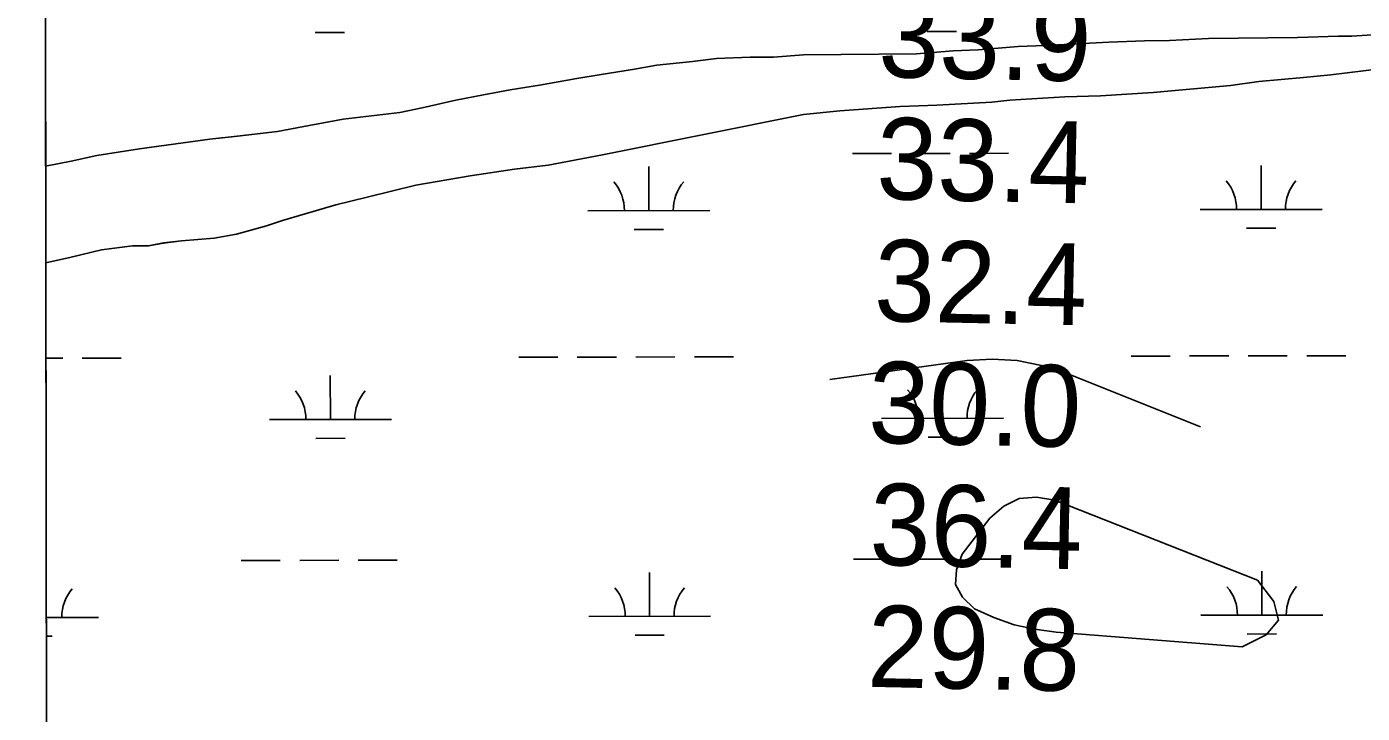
# Model space of a CAD drawing. Extents: x 3329297 to 3367176, y 649250 to 674653.
# Drawn here: x 3333403 to 3334498, y 661713 to 662276 of the extents above; entities that cross this region are included whole.
import ezdxf

# ---------------------------------------------------------------- set-up
doc = ezdxf.new("R2010")
doc.units = 0
for name, color, linetype in [('V-GRID-FRAM', 7, 'Continuous'), ('V-RIVR-EDGE', 7, 'Continuous'), ('V-RIVR-RANG', 7, 'Continuous'), ('V-SITE-VEGE', 7, 'Continuous'), ('V-TOPO-MINR', 7, 'Continuous'), ('V-WETL-SWMP', 7, 'Continuous')]:
    doc.layers.add(name, color=color, linetype=linetype)

msp = doc.modelspace()

# ---------------------------------------------------------------- linework, layer by layer
at = {"layer": 'V-GRID-FRAM'}
msp.add_lwpolyline([(3333403.5, 672816.3), (3364945.5, 672875.9), (3364987.9, 654691.7), (3333429.9, 654632), (3333403.5, 672816.3)], dxfattribs=at)
at = {"layer": 'V-RIVR-EDGE'}
msp.add_spline([(3333408.7, 669402.3), (3333456.2, 669390.7), (3333480.6, 669386.5), (3333498.4, 669381.9), (3333510.9, 669380.2), (3333522.1, 669375.2), (3333537.8, 669370.2), (3333569.3, 669364.3), (3333591.6, 669358.9), (3333623.1, 669349.7), (3333650.9, 669341.3), (3333676.1, 669333), (3333726.3, 669319.2), (3333778.9, 669302), (3333791.7, 669299.5), (3333813.6, 669293.3), (3333833.9, 669285.7), (3333853.8, 669277.4), (3333866.2, 669277.4), (3333927.5, 669258.6), (3333978.9, 669241), (3334054.7, 669220.1), (3334082, 669212.6), (3334104.4, 669205.9), (3334133.4, 669195.1), (3334212.1, 669170), (3334258.9, 669154.5), (3334287.5, 669144.9), (3334323.9, 669134.5), (3334362.8, 669121.1), (3334397.6, 669109.4), (3334435.3, 669094.8), (3334441.9, 669091.5), (3334451.9, 669089.8), (3334461, 669084), (3334464.7, 669082.7), (3334470.5, 669083.6), (3334476.3, 669080.2), (3334476.7, 669076.1), (3334486.6, 669072.7), (3334503.2, 669071.9), (3334523.5, 669067.3), (3334538.4, 669061.4), (3334550.4, 669055.2), (3334564.9, 669046.8), (3334575.7, 669042.7), (3334598.9, 669036.4), (3334626.2, 669030.9), (3334690.8, 669018.8), (3334721.1, 669015.8), (3334733.1, 669015.8), (3334745.1, 669011.2), (3334755.1, 669009.5), (3334769.6, 669008.6), (3334791.1, 669004.4), (3334799.8, 669004.4), (3334813.5, 669004.8), (3334832.6, 668999.8), (3334841.7, 668998.5), (3334844.6, 668994.8), (3334857, 668990.2), (3334864, 668983.9), (3334870.2, 668977.7), (3334876.8, 668970.2), (3334882.2, 668968.6), (3334894.6, 668965.6), (3334904.2, 668965.6), (3334918.3, 668964.3), (3334926.6, 668963.5), (3334936.1, 668958.5), (3334945.2, 668949.3), (3334956.8, 668941), (3334959.7, 668941.4), (3334971.7, 668941.4), (3334983.3, 668941.8), (3334993.2, 668938.9), (3335003.6, 668932.2), (3335011.4, 668925.1), (3335021.8, 668920.1), (3335034.2, 668916), (3335054.9, 668911.8), (3335057, 668908.9), (3335064.8, 668903.9), (3335073.5, 668900.1), (3335081, 668898), (3335087.6, 668898), (3335095.1, 668898), (3335097.6, 668895.1), (3335105, 668888.4), (3335114.1, 668882.2), (3335138.1, 668873), (3335159.7, 668864.2), (3335185.7, 668850.5), (3335195.2, 668838.9), (3335211, 668830.1), (3335229.2, 668825.5), (3335249.9, 668817.6), (3335252.4, 668811.4), (3335261.5, 668805.6), (3335272.7, 668798.5), (3335296.3, 668792.6), (3335327.3, 668778.4), (3335359.2, 668761.8), (3335399.3, 668739.7), (3335432.5, 668723.5), (3335466.4, 668708.1), (3335508.6, 668689.3), (3335535.5, 668674.3), (3335584, 668653.1), (3335614.6, 668638.1), (3335645.3, 668624.7), (3335682.1, 668600.6), (3335715.2, 668580.6), (3335752.5, 668561.5), (3335771.9, 668553.1), (3335793.9, 668548.5), (3335846.4, 668524.7), (3335870.9, 668514.7), (3335887.9, 668509.3), (3335894.9, 668501), (3335912.7, 668488.1), (3335927.6, 668478.1), (3335958.6, 668466.4), (3335986.8, 668452.7), (3336001.3, 668442.7), (3336018.7, 668434.4), (3336038.9, 668426.9), (3336117.2, 668387.3), (3336184.2, 668349), (3336223.1, 668326.5), (3336257.5, 668305.7), (3336289.4, 668284.5), (3336317.1, 668269.5), (3336332.8, 668261.6), (3336456.6, 668198.7), (3336509.2, 668170.8), (3336541.4, 668152.9), (3336585.7, 668130), (3336625.9, 668110.8), (3336652.8, 668097.9), (3336753.4, 668040), (3336798.1, 668013.8), (3336819.6, 668001.3), (3336844, 667986.8), (3336862.2, 667973.9), (3336893.7, 667952.2), (3336928, 667933.1), (3336960.3, 667914.8), (3336990.5, 667894.8), (3337029.4, 667867.8), (3337069.1, 667842.4), (3337101, 667829.5), (3337126.7, 667818.2), (3337166, 667790.3), (3337200.4, 667767.9), (3337228.5, 667747.5), (3337263.3, 667726.3), (3337288.9, 667709.2), (3337372.5, 667657.2), (3337387.8, 667642.6), (3337413.9, 667621.9), (3337448.6, 667598.6), (3337473.4, 667578.6), (3337509, 667550.7), (3337579.4, 667503.3), (3337621.1, 667469.6), (3337665, 667431), (3337708, 667391.1), (3337739.8, 667359.1), (3337772.9, 667327.1), (3337812.2, 667288.5), (3337827.1, 667271.4), (3337829.5, 667264.4), (3337842.8, 667251.5), (3337873.4, 667227.8), (3337886.2, 667214.9), (3337903.2, 667197.9), (3337949.4, 667144.7), (3337971.4, 667123.5), (3337996.2, 667096.5), (3338024.3, 667069.9), (3338047, 667044.6), (3338075.5, 667011.8), (3338104.9, 666976.9), (3338113.6, 666965.2), (3338176.8, 666889.6), (3338206.1, 666850.2), (3338224.3, 666825.3), (3338246.2, 666798.3), (3338263.5, 666774.2), (3338301.9, 666718.6), (3338311.9, 666704.5), (3338328, 666683.3), (3338335.4, 666667.9), (3338348.6, 666644.3), (3338362.6, 666627.2), (3338385.4, 666599.4), (3338404.4, 666574.5), (3338412.6, 666562), (3338414.7, 666551.3), (3338422.1, 666533), (3338443.1, 666494), (3338455.9, 666472), (3338475.4, 666449.6), (3338483.2, 666442.9), (3338498.1, 666425), (3338521.6, 666381.9), (3338562.5, 666317.5), (3338585.6, 666290.5), (3338600.5, 666260.7), (3338619.9, 666220), (3338640.9, 666179.7), (3338652.5, 666165.2), (3338660.7, 666148.6), (3338709, 666053.1), (3338735.4, 666007.5), (3338756.4, 665971.4), (3338777.1, 665937.3), (3338810.1, 665887.1), (3338828.7, 665846.4), (3338853.8, 665796.6), (3338873.6, 665751.8), (3338895.1, 665712.8), (3338903.7, 665692.1), (3338916.5, 665665.9), (3338933.8, 665635.2), (3338944.1, 665609.5), (3338956.5, 665578.8), (3338961.9, 665565.5), (3338976.7, 665543.1), (3338985, 665527.7), (3338995.3, 665511.1), (3339011.8, 665472.1), (3339026.6, 665438.9), (3339039.8, 665412.8), (3339047.6, 665382.9), (3339085.5, 665290), (3339099.5, 665253.9), (3339113.5, 665222.8), (3339126.3, 665192.5), (3339138.7, 665160.5), (3339164.2, 665092.5), (3339180.3, 665056), (3339203.7, 664990.8), (3339215.7, 664956.4), (3339231.3, 664897.5), (3339241.1, 664863.5), (3339253.9, 664825.8), (3339262.1, 664798.4), (3339275.3, 664761.9), (3339290.5, 664724.5), (3339306.2, 664692.2), (3339319, 664656.5), (3339324.3, 664636.6), (3339336.6, 664597.2), (3339352.3, 664567.7), (3339365.5, 664538.2), (3339372.1, 664519.6), (3339374.1, 664493), (3339373.2, 664478.9), (3339373.2, 664471.1), (3339377.3, 664449.9), (3339393.8, 664419.2), (3339410.3, 664384.8), (3339423.5, 664344.9), (3339458.5, 664257.4), (3339470, 664219.2), (3339470.4, 664207.2), (3339477.8, 664185.7), (3339481.1, 664164.9), (3339486.4, 664140), (3339490.1, 664124.3), (3339499.6, 664107.3), (3339512.7, 664069.9), (3339523.8, 664028.4), (3339527.5, 663998.2), (3339528.2, 663969.6), (3339525.7, 663951.8), (3339522.4, 663945.6), (3339521.1, 663939.3), (3339524, 663925.2), (3339554.1, 663875), (3339569.4, 663836), (3339574.3, 663803.7), (3339577.1, 663774.2), (3339586.9, 663730.7), (3339599.7, 663691.3), (3339610.3, 663646.9), (3339623.1, 663615.8), (3339630.5, 663595.9), (3339633.8, 663595.9), (3339643, 663599.2), (3339643, 663594.2), (3339646.2, 663566), (3339654.4, 663535.7), (3339664.3, 663503.8), (3339677, 663465.2), (3339691.9, 663427), (3339697.2, 663406.7), (3339697.2, 663392.2), (3339697.1, 663381), (3339704.9, 663354.5), (3339710.7, 663325.4), (3339723.8, 663284.4), (3339738.7, 663247.4), (3339746.1, 663222.6), (3339747.7, 663203.1), (3339746.4, 663183.6), (3339745.5, 663154.6), (3339745, 663130.5), (3339742.9, 663119.4), (3339739.6, 663107.3), (3339737, 663082.5), (3339735.3, 663062.2), (3339736.9, 663039.8), (3339742.2, 663016.6), (3339743.9, 663011.6), (3339748, 663011.6), (3339751.8, 663009.5), (3339753.8, 663002.4), (3339760, 662996.6), (3339761.2, 662990.8), (3339763.7, 662975.9), (3339763.2, 662954.8), (3339760.7, 662930.3), (3339757.8, 662927.8), (3339749.1, 662927.4), (3339743.3, 662927.4), (3339738.7, 662924.1), (3339735, 662917.9), (3339730.4, 662915.9), (3339727.5, 662912.2), (3339727.1, 662907.6), (3339732.4, 662900.1), (3339737.4, 662884.4), (3339741.9, 662869.4), (3339745.2, 662866.1), (3339748.1, 662867.3), (3339750.6, 662877.3), (3339752.7, 662878.9), (3339754.3, 662875.6), (3339755.6, 662867.7), (3339761.7, 662859), (3339764.2, 662850.7), (3339762.5, 662844.1), (3339761.7, 662822.1), (3339758.3, 662812.6), (3339756.6, 662801.8), (3339759.5, 662784), (3339757.4, 662779.4), (3339754.9, 662768.7), (3339755.3, 662757.1), (3339757.7, 662749.6), (3339761.9, 662739.6), (3339755.6, 662731), (3339746.5, 662711.1), (3339737.7, 662704.1), (3339732.8, 662703.2), (3339730.3, 662699.9), (3339733.6, 662689.6), (3339736.8, 662677.1), (3339737.2, 662668), (3339731.8, 662659.3), (3339726.4, 662644.4), (3339724.3, 662641.1), (3339729.7, 662633.2), (3339729.7, 662627.4), (3339727.2, 662625.3), (3339721.8, 662625.8), (3339721.8, 662615.4), (3339723, 662597.2), (3339722.9, 662560.7), (3339725.3, 662535.4), (3339725.3, 662520.5), (3339726.8, 662486.5), (3339724.3, 662463.3), (3339713, 662438.4), (3339703.9, 662416.9), (3339699.7, 662391.6), (3339692.9, 662333.2), (3339688.2, 662298), (3339687.4, 662274.4), (3339683.6, 662256.1), (3339676.1, 662240), (3339666.1, 662216.8), (3339659.8, 662192.8), (3339656.8, 662171.6), (3339654.7, 662126.1), (3339650.4, 662090.8), (3339644.5, 662058.5), (3339643.7, 662039.5), (3339638.2, 662015.4), (3339634.4, 661998.4), (3339628.6, 661971.9), (3339619, 661945.8), (3339616.5, 661933), (3339617.2, 661907.3), (3339619.6, 661875), (3339617.1, 661854.7), (3339612.9, 661845.6), (3339610.8, 661836.4), (3339610, 661829.8), (3339610, 661820.3), (3339609.9, 661810.7), (3339603.7, 661804.1), (3339600.8, 661799.6), (3339598.7, 661785.1), (3339594.9, 661775.6), (3339590.3, 661759.4), (3339588.6, 661741.2), (3339585.7, 661733.3), (3339580.7, 661727.5), (3339574.1, 661723.8), (3339572.8, 661715.9), (3339571.9, 661693.5), (3339564, 661655), (3339553.9, 661613.6), (3339540.6, 661574.7), (3339527.6, 661533.7), (3339508.4, 661497.2), (3339490.1, 661455.8), (3339486.8, 661446.7), (3339487.1, 661432.6), (3339486.3, 661412.3), (3339484.6, 661404), (3339476.7, 661391.6), (3339467.9, 661378.8), (3339453, 661365.1), (3339446.8, 661363.5), (3339441, 661363.1), (3339433.9, 661354.8), (3339423.5, 661346.2), (3339398.2, 661334.6), (3339381.2, 661326.8), (3339370, 661319.8), (3339357.5, 661305.3), (3339344.6, 661280), (3339333, 661269.7), (3339320.9, 661263.5), (3339313.9, 661263.1), (3339310.2, 661266), (3339308.1, 661271.8), (3339302.7, 661282.2), (3339298.6, 661286.4), (3339290.7, 661288.9), (3339284.9, 661288.9), (3339275, 661285.6), (3339261.3, 661273.2), (3339255.5, 661266.6), (3339248.8, 661265.8), (3339234.7, 661264.6), (3339224.4, 661264.2), (3339216.5, 661259.2), (3339211.9, 661252.2), (3339209.4, 661248.5), (3339211, 661240.6), (3339215.6, 661229.4), (3339215.5, 661208.2), (3339213.4, 661191.2), (3339208.8, 661185), (3339198.8, 661169.3), (3339191, 661161.9), (3339179.3, 661161.1), (3339154.5, 661165.7), (3339128, 661171.1), (3339111.4, 661176.2), (3339105.2, 661176.2), (3339096.9, 661174.1), (3339090.7, 661168.7), (3339085.7, 661157.2), (3339071.9, 661143.1), (3339054.9, 661129.9), (3339020.1, 661118.8), (3338993.5, 661110.1), (3338978.6, 661099.8), (3338965.3, 661086.2), (3338953.6, 661064.6), (3338937.4, 661039)], degree=3, dxfattribs=at)
at = {"layer": 'V-SITE-VEGE'}
for p, q in [((3333419, 662161.1), (3333414.7, 665088.7)), ((3334527.8, 662270.4), (3334489.9, 662267.8)), ((3334216.3, 662259.2), (3334183.4, 662256.7)), ((3334238.2, 662260.2), (3334216.3, 662259.2)), ((3334290.7, 662262.9), (3334238.2, 662260.2)), ((3334319.9, 662263.9), (3334290.7, 662262.9)), ((3334340.3, 662264.1), (3334319.9, 662263.9)), ((3334372.4, 662265.9), (3334340.3, 662264.1)), ((3334445.4, 662266.6), (3334372.4, 662265.9)), ((3334478.9, 662267.7), (3334445.4, 662266.6)), ((3334489.9, 662267.8), (3334478.9, 662267.7)), ((3333968.9, 662249.5), (3333949.2, 662247.1)), ((3333996.7, 662250.5), (3333968.9, 662249.5)), ((3334015.6, 662250.7), (3333996.7, 662250.5)), ((3334040.4, 662252.4), (3334015.6, 662250.7)), ((3334133.1, 662253.3), (3334040.4, 662252.4)), ((3334163, 662255.8), (3334133.1, 662253.3)), ((3334183.4, 662256.7), (3334163, 662255.8)), ((3333901.9, 662240.8), (3333872.7, 662236.1)), ((3333920.1, 662243.9), (3333901.9, 662240.8)), ((3333949.2, 662247.1), (3333920.1, 662243.9)), ((3334472.7, 662236.2), (3334512.8, 662241)), ((3333823.9, 662227.6), (3333799.8, 662223.7)), ((3333854.5, 662233), (3333823.9, 662227.6)), ((3333872.7, 662236.1), (3333854.5, 662233)), ((3334326.9, 662221.7), (3334390.3, 662227.4)), ((3334390.3, 662227.4), (3334413.6, 662230.5)), ((3334413.6, 662230.5), (3334450.1, 662233.8)), ((3334450.1, 662233.8), (3334472.7, 662236.2)), ((3333778, 662219.8), (3333755.4, 662215.2)), ((3333799.8, 662223.7), (3333778, 662219.8)), ((3334209.4, 662215.4), (3334254.6, 662218)), ((3334254.6, 662218), (3334283.8, 662219)), ((3334283.8, 662219), (3334326.9, 662221.7)), ((3333709.5, 662205.3), (3333662.9, 662199.7)), ((3333727.7, 662209.1), (3333709.5, 662205.3)), ((3333755.4, 662215.2), (3333727.7, 662209.1)), ((3334040.2, 662203.5), (3334070.1, 662206.7)), ((3334070.1, 662206.7), (3334119.7, 662210.1)), ((3334119.7, 662210.1), (3334149.6, 662211.1)), ((3334149.6, 662211.1), (3334194.8, 662213.8)), ((3334194.8, 662213.8), (3334209.4, 662215.4)), ((3333630.8, 662193.6), (3333609, 662189.7)), ((3333662.9, 662199.7), (3333630.8, 662193.6)), ((3333875.6, 662170.4), (3334040.2, 662203.5)), ((3333553.5, 662183.3), (3333496, 662175.4)), ((3333576.1, 662185.7), (3333553.5, 662183.3)), ((3333609, 662189.7), (3333576.1, 662185.7)), ((3333496, 662175.4), (3333461, 662170)), ((3333439.9, 662165.4), (3333419, 662161.1)), ((3333461, 662170), (3333439.9, 662165.4)), ((3333803.4, 662158.8), (3333831.1, 662162)), ((3333831.1, 662162), (3333875.6, 662170.4)), ((3333722.5, 662145.6), (3333767, 662153.3)), ((3333767, 662153.3), (3333803.4, 662158.8)), ((3333682.5, 662135.7), (3333722.5, 662145.6)), ((3333613.3, 662116.7), (3333657, 662129.6)), ((3333657, 662129.6), (3333682.5, 662135.7)), ((3333575.5, 662105.4), (3333600.2, 662112.2)), ((3333600.2, 662112.2), (3333613.3, 662116.7)), ((3333464.7, 662092.6), (3333490.2, 662095.8)), ((3333490.2, 662095.8), (3333503.3, 662095.9)), ((3333503.3, 662095.9), (3333515.7, 662098.2)), ((3333515.7, 662098.2), (3333530.3, 662099.9)), ((3333530.3, 662099.9), (3333557.3, 662102.3)), ((3333557.3, 662102.3), (3333575.5, 662105.4)), ((3333419.1, 662081.9), (3333439.9, 662086.5)), ((3333439.9, 662086.5), (3333464.7, 662092.6)), ((3333420.1, 661429.6), (3333419.1, 662081.9))]:
    msp.add_line(p, q, dxfattribs=at)
at = {"layer": 'V-TOPO-MINR'}
for points in [[(3334365.7, 661947.5), (3334255.2, 661991.8), (3334235.5, 661997.9), (3334215.4, 662002), (3334195.1, 662002.9), (3334174.4, 662001.8), (3334062, 661986.4)], [(3334165, 661818.3), (3334165.7, 661830.2), (3334170.5, 661843), (3334193.1, 661872.5), (3334204.6, 661882.4), (3334217.2, 661888.8), (3334231.3, 661889.8), (3334246.3, 661887.3), (3334412.5, 661821.7), (3334425.8, 661804.3), (3334429.7, 661789), (3334419.5, 661777), (3334399.9, 661767.2), (3334247.4, 661779.1), (3334229.9, 661781.5), (3334212.9, 661785.3), (3334196.4, 661791.1), (3334180.4, 661798.3), (3334170.6, 661807.8), (3334165, 661818.3)]]:
    msp.add_lwpolyline(points, dxfattribs=at)
at = {"layer": 'V-WETL-SWMP'}
for p, q in [((3333419, 662161.1), (3333414.7, 665088.7)), ((3333639.9, 662270.7), (3333663.9, 662270.8)), ((3334141.8, 662271.7), (3334165.8, 662271.7)), ((3334527.8, 662270.4), (3334489.9, 662267.8)), ((3334216.3, 662259.2), (3334183.4, 662256.7)), ((3334238.2, 662260.2), (3334216.3, 662259.2)), ((3334290.7, 662262.9), (3334238.2, 662260.2)), ((3334319.9, 662263.9), (3334290.7, 662262.9)), ((3334340.3, 662264.1), (3334319.9, 662263.9)), ((3334372.4, 662265.9), (3334340.3, 662264.1)), ((3334445.4, 662266.6), (3334372.4, 662265.9)), ((3334478.9, 662267.7), (3334445.4, 662266.6)), ((3334489.9, 662267.8), (3334478.9, 662267.7)), ((3333968.9, 662249.5), (3333949.2, 662247.1)), ((3333996.7, 662250.5), (3333968.9, 662249.5)), ((3334015.6, 662250.7), (3333996.7, 662250.5)), ((3334040.4, 662252.4), (3334015.6, 662250.7)), ((3334133.1, 662253.3), (3334040.4, 662252.4)), ((3334163, 662255.8), (3334133.1, 662253.3)), ((3334183.4, 662256.7), (3334163, 662255.8)), ((3333901.9, 662240.8), (3333872.7, 662236.1)), ((3333920.1, 662243.9), (3333901.9, 662240.8)), ((3333949.2, 662247.1), (3333920.1, 662243.9)), ((3334472.7, 662236.2), (3334512.8, 662241)), ((3333823.9, 662227.6), (3333799.9, 662223.7)), ((3333854.5, 662233), (3333823.9, 662227.6)), ((3333872.7, 662236.1), (3333854.5, 662233)), ((3334326.9, 662221.7), (3334390.3, 662227.4)), ((3334390.3, 662227.4), (3334413.6, 662230.5)), ((3334413.6, 662230.5), (3334450.1, 662233.8)), ((3334450.1, 662233.8), (3334472.7, 662236.2)), ((3333778, 662219.8), (3333755.4, 662215.2)), ((3333799.9, 662223.7), (3333778, 662219.8)), ((3334209.4, 662215.4), (3334254.6, 662218)), ((3334254.6, 662218), (3334283.8, 662219)), ((3334283.8, 662219), (3334326.9, 662221.7)), ((3333709.5, 662205.3), (3333662.9, 662199.7)), ((3333727.7, 662209.1), (3333709.5, 662205.3)), ((3333755.4, 662215.2), (3333727.7, 662209.1)), ((3334040.2, 662203.5), (3334070.1, 662206.7)), ((3334070.1, 662206.7), (3334119.7, 662210.1)), ((3334119.7, 662210.1), (3334149.6, 662211.1)), ((3334149.6, 662211.1), (3334194.8, 662213.8)), ((3334194.8, 662213.8), (3334209.4, 662215.4)), ((3333630.8, 662193.6), (3333609, 662189.7)), ((3333662.9, 662199.7), (3333630.8, 662193.6)), ((3333875.6, 662170.4), (3334040.2, 662203.5)), ((3333553.5, 662183.3), (3333496, 662175.4)), ((3333576.2, 662185.7), (3333553.5, 662183.3)), ((3333609, 662189.7), (3333576.2, 662185.7)), ((3333496, 662175.4), (3333461, 662170)), ((3334128.5, 662171.6), (3334160.5, 662171.7)), ((3334176.5, 662171.7), (3334208.5, 662171.8)), ((3333439.9, 662165.4), (3333419, 662161.1)), ((3333461, 662170), (3333439.9, 662165.4)), ((3333803.4, 662158.8), (3333831.1, 662162)), ((3333831.1, 662162), (3333875.6, 662170.4)), ((3333913.6, 662124.8), (3333913.5, 662160.8)), ((3334080.5, 662171.5), (3334112.5, 662171.6)), ((3334415.5, 662125.7), (3334415.4, 662161.7)), ((3333722.5, 662145.6), (3333767, 662153.3)), ((3333767, 662153.3), (3333803.4, 662158.8)), ((3333682.5, 662135.7), (3333722.5, 662145.6)), ((3333613.3, 662116.7), (3333657, 662129.6)), ((3333657, 662129.6), (3333682.5, 662135.7)), ((3333863.6, 662124.7), (3333963.6, 662124.9)), ((3334365.5, 662125.7), (3334465.5, 662125.8)), ((3333575.5, 662105.4), (3333600.2, 662112.2)), ((3333600.2, 662112.2), (3333613.3, 662116.7)), ((3333901.6, 662109.3), (3333925.6, 662109.4)), ((3334403.5, 662110.3), (3334427.5, 662110.3)), ((3333464.7, 662092.6), (3333490.2, 662095.8)), ((3333490.2, 662095.8), (3333503.3, 662095.9)), ((3333503.3, 662095.9), (3333515.7, 662098.3)), ((3333515.7, 662098.3), (3333530.3, 662099.9)), ((3333530.3, 662099.9), (3333557.3, 662102.3)), ((3333557.3, 662102.3), (3333575.5, 662105.4)), ((3333419.1, 662081.9), (3333439.9, 662086.5)), ((3333439.9, 662086.5), (3333464.7, 662092.6)), ((3333420.1, 661429.6), (3333419.1, 662081.9)), ((3333419.2, 662003.8), (3333433, 662003.8)), ((3333449, 662003.8), (3333481, 662003.9)), ((3333806.9, 662004.5), (3333838.9, 662004.6)), ((3333854.9, 662004.6), (3333886.9, 662004.7)), ((3333902.9, 662004.7), (3333934.9, 662004.8)), ((3333950.9, 662004.8), (3333982.9, 662004.9)), ((3334308.9, 662005.5), (3334340.9, 662005.5)), ((3334356.9, 662005.6), (3334388.9, 662005.6)), ((3334404.9, 662005.7), (3334436.9, 662005.7)), ((3334452.9, 662005.7), (3334484.9, 662005.8)), ((3333652.5, 661953.5), (3333652.4, 661989.5)), ((3334154.4, 661954.4), (3334154.3, 661990.4)), ((3333602.5, 661953.4), (3333702.5, 661953.6)), ((3334104.4, 661954.3), (3334204.4, 661954.5)), ((3333640.5, 661938), (3333664.5, 661938.1)), ((3334142.4, 661939), (3334166.4, 661939)), ((3333579.3, 661837.9), (3333611.3, 661838)), ((3333627.3, 661838), (3333659.3, 661838.1)), ((3333675.3, 661838.1), (3333707.3, 661838.2)), ((3334081.2, 661838.9), (3334113.2, 661838.9)), ((3334129.2, 661839), (3334161.2, 661839)), ((3334177.2, 661839.1), (3334209.2, 661839.1)), ((3333914.2, 661792.1), (3333914.1, 661828.1)), ((3334416.1, 661793.1), (3334416, 661829.1)), ((3333419.5, 661791.2), (3333462.3, 661791.3)), ((3333864.2, 661792), (3333964.2, 661792.2)), ((3334366.1, 661793), (3334466.1, 661793.2)), ((3334404.1, 661777.6), (3334428.1, 661777.7)), ((3333419.6, 661775.8), (3333424.3, 661775.8)), ((3333902.2, 661776.7), (3333926.2, 661776.7))]:
    msp.add_line(p, q, dxfattribs=at)
for centre, start, end in [((3333858.3, 662125.2), 359.3365, 40.8801), ((3333968.8, 662125.4), 139.3365, 180.8801), ((3334360.2, 662126.1), 359.3365, 40.8801), ((3334470.7, 662126.3), 139.3365, 180.8801), ((3333597.2, 661953.9), 359.3365, 40.8801), ((3333707.7, 661954.1), 139.3365, 180.8801), ((3334099.1, 661954.8), 359.3365, 40.8801), ((3334209.6, 661955), 139.3365, 180.8801), ((3333467.5, 661791.8), 139.3365, 180.8801), ((3333859, 661792.5), 359.3365, 40.8801), ((3333969.4, 661792.7), 139.3365, 180.8801), ((3334360.9, 661793.4), 359.3365, 40.8801), ((3334471.3, 661793.7), 139.3365, 180.8801)]:
    msp.add_arc(centre, 35.2, start, end, dxfattribs=at)

# ---------------------------------------------------------------- texts
at = {"layer": 'V-RIVR-RANG'}
for s, p in [('33.9', (3334101.3, 662234.3)), ('33.4', (3334099.7, 662134.3)), ('32.4', (3334097.8, 662034.3)), ('30.0', (3334093, 661934.4)), ('36.4', (3334094.1, 661834.4)), ('29.8', (3334092.2, 661734.4))]:
    msp.add_text(s, height=67, rotation=358.7883, dxfattribs=at).set_placement(p)

doc.saveas('drawing.dxf')
